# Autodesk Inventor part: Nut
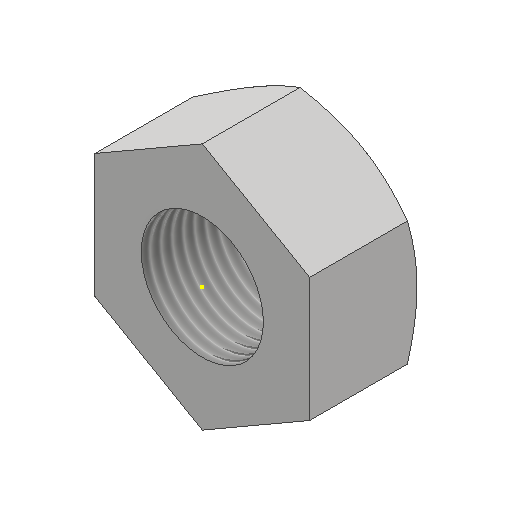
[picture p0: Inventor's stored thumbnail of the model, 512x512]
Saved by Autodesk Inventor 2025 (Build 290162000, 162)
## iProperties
Created: 2016-05
Part Number: Nut
Material: Generic
Document SubType Name: Modeling
Designer: CADCIM
Density: 1 g/cm^3
Appearance: Default
Author: CADCIM
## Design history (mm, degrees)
sketch "Sketch1"
  geometry: L1 (0, -33.255)-(-28.8, -16.628); L2 (-28.8, -16.628)-(-28.8, 16.628); L3 (-28.8, 16.628)-(0, 33.255); L4 (0, 33.255)-(28.8, 16.628); L5 (28.8, 16.628)-(28.8, -16.628); L6 (28.8, -16.628)-(0, -33.255); 2 further points
  constraints: 12 end point, 1 coincident, 13 other
  dimensions: "d0" = 57.6 distance between parallel lines of L2 L5
extrude "Extrusion1" new body sketch "Sketch1" stored distance "d1" = 28.8; taper "d2" = 0 deg
sketch "Sketch2"
  geometry: L1 (0, 33.255)-(-28.8, 16.628) reference; C1 r 28.8 at (0, 0); 1 further point
  constraints: 1 centre point, 1 coincident, 1 tangent
extrude "Extrusion2" sketch "Sketch2" distance "d3" = 28.8; taper "d4" = 60 deg
hole "Hole1" diameter "d7" = 32.752; stored, may be unused: countersink angle "d11" = 90 deg, drill point angle "d13" = 118 deg; dims "d5" = 10, "d6" = 10, "d8" = 72, "d9" = 4, "d10" = 2, "d12" = 85.1
body "Solid1"
sketch "Sketch3"
  geometry: 1 further point
